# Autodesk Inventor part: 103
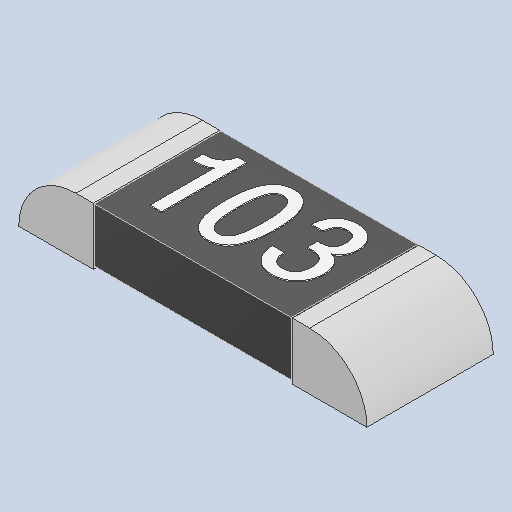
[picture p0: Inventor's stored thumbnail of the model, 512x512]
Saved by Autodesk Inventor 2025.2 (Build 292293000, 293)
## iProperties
Created: 2025-04
Part Number: 103
Material: Generic
Description: PART--DESC
Document SubType Name: Modeling
Designer: BennF
Density: 1 g/cm^3
Appearance: Default
Author: BennF
Revision Number: NONE
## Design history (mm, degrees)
feature "Solid"
feature "pin"
feature "1"
feature "0"
feature "3"
body "Solid1"
body "Solid2"
body "Solid3"
body "Solid4"
body "Solid5"
